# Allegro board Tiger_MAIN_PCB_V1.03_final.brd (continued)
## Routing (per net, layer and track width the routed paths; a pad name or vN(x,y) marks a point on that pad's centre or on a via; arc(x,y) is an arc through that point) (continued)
GND_EARTH: length 5.3
  TOP w0.406: v2(100.89,25.46) C401.1 102.17,28.36 C400.1 102.17,28.63 C402.2 102.18,29.41 C399.2
  vias: v1(81.7,22.25) v1(81.7,21.36) v1(81.7,20.47) v2(107.05,42.35) v2(107.05,40.53) v2(107.06,39.4) v2(107.06,37.58) v2(108.16,29.18) v2(108.2,42.12) v2(108.21,40.37) v2(108.27,38.2) v2(108.22,32.34) v2(108.29,35.24)
V1.05A_PWRGD: length 114.6
  TOP w0.254: v2(164.11,48.34) R767.1 164.89,47.9 165.68,47.11 165.68,46.63 165.43,46.38 U41.6
  LAY6 w0.102: v2(164.11,48.34) 163.26,49.2 156.67,49.2 155.35,47.87 146.17,47.87 142.89,51.15 118.33,51.15 113.42,56.07 98.24,56.07 97.35,56.96 92.7,56.96 91.94,57.72 73.65,57.72 72.97,57.03 66.45,57.03 66.02,56.6 v2(61.12,56.6)
  BOTTOM w0.102: v2(61.12,56.6) 61.12,56.97 60.71,57.37 60.08,57.37 59.92,57.22 U22.34
V1.5S_PWRGD: length 113.8
  TOP w0.102: v2(138.59,57.5) 138.6,57.5 139.04,57.95 144.57,57.95 144.78,57.74 R537.2 144.96,57.24 U35.7
  LAY3 w0.102: v2(50.23,67.89) 50.68,67.45 50.68,57.81 v2(50.93,57.55)
  LAY6 w0.102: v2(138.59,57.5) 138.26,57.83 135.39,57.83 135.09,57.53 133.5,57.53 132.73,58.3 119.21,58.3 116.64,60.87 115.58,60.87 114.67,61.79 114.67,62.55 114.28,62.94 82.47,62.94 79.88,65.53 66.43,65.53 64.39,67.56 50.56,67.56 v2(50.23,67.89)
  BOTTOM w0.102: v2(50.93,57.55) 50.72,57.34 U22.57
V1.8A_PWRGD: length 2.5
  BOTTOM w0.203: U70.4 155.05,51.04 155.35,51.34 156.62,51.34 R774.2
V1P0_DRVH: length 13.9
  TOP w0.254: U41.13 161.51,44.25 161.05,43.79
  TOP w0.635: v1(160.15,43.44) 160.7,43.44 161.05,43.79 ; R765.1 159.74,53.22 v1(159.89,53.07)
  LAY3 w0.635: v1(160.15,43.44) 159.63,43.44 158.64,44.43 158.64,48.52 159.89,49.77 v1(159.89,53.07)
V1P0_DRVL: length 2.2
  TOP w0.254: U41.9 161.51,46.66
  TOP w0.635: 161.51,46.66 161.51,48.61 R768.1
V1P0_LL: length 35.6
  TOP w0.254: U41.12 160.92,44.88 160.83,44.79 ; R392.2 165.58,40.83 165.08,40.33 163.82,40.33 163.07,41.09 163.07,41.8 C344.1 163.05,42.02 v2(162.73,42.34)
  TOP w0.635: 160.83,44.79 160.46,44.42 v1(159.97,44.42)
  LAY3 w0.635: v1(159.97,44.42) 161.61,46.06 v1(161.61,57.01)
  BOTTOM w0.254: v2(162.73,42.34) 161.51,43.56 161.51,47.82 161.96,48.27 161.96,56.32 v2(162.54,56.9)
VBAT: length 2.4
  BOTTOM w0.203: U22.3 62.8,69.46 R381.2 63.2,69.86 R390.2
VCC1_USB3.0: length 4
  TOP w0.635: CN36.1 v1(11.95,92.82)
  BOTTOM w0.305: R339.2 19.77,89.27 19.77,88.26 19.18,87.66
VCC2_USB3.0: length 3.5
  TOP w0.762: v1(38.86,92.15) 38.85,92.16 CN24.1
  BOTTOM w0.305: R559.2 46.17,88.93
VCC_8625: length 41
  TOP w0.305: R2999.2 134.55,76.1 134.05,75.6 ; 132.21,75.6 131.53,75.6 ; 132.21,75.6 131.88,75.93 131.88,75.95 ; 132.21,75.6 134.05,75.6 ; 131.53,75.6 130.32,75.6 130,75.92 U2527.8 130,78.71 R2988.2 ; 131.53,75.6 131.88,75.95 ; 131.88,75.95 131.88,78.67 R2998.2 ; 134.05,75.6 135.04,74.61 U2525.8 135.6,75.53 v2(136.33,76.26) 136.34,76.27 R2991.1 ; R2992.1 v2(140.45,76.27)
  LAY3 w0.305: v2(140.45,76.27) 142.1,76.27 143.02,77.19 146.15,77.19 v2(147.73,78.76)
  BOTTOM w0.203: U2526.13 144.14,82.01 144.58,81.58 144.58,81.34 144.25,81.34 143.98,81.61 U2526.14
  BOTTOM w0.305: v2(136.33,76.26) 140.44,76.26 v2(140.45,76.27)
  BOTTOM w0.508: v2(147.73,78.76) 147.6,78.89 146.55,78.89 145.7,79.75 C2766.1 145.53,79.75 144.58,80.7 144.58,81.34
  BOTTOM w0.762: FB45.1 147.87,77.71 FB39.1 147.87,78.62 v2(147.73,78.76)
VCC_USB2: length 6.6
  TOP w0.203: R569.2 44.11,24.26 44.11,19.64 F4.2
VCC_USB3: length 3.4
  TOP w0.203: R570.2 62.7,17.44 63.07,17.06
VCCCORE_SENSE: length 80.5
  TOP w0.076: U1.E32 v2(205.19,74.95)
  LAY3 w0.305: v2(205.19,74.95) 206.22,75.98 206.22,81.63 208.65,84.06 209.41,84.06 210.57,85.22 220.35,85.22 221.06,85.93 225.27,85.93 226.47,84.73 233.41,84.73 236.14,82 241.25,82 242.55,83.29 248.35,83.29 250,84.95 250,97.48 247.88,99.6 244.61,99.6 v2(241.74,102.47)
  BOTTOM w0.305: R683.2 241.27,102.94 v2(241.74,102.47)
VCCCORE_SENSE_IC: length 9.1
  BOTTOM w0.203: U103.17 238.57,92.14
  BOTTOM w0.305: 238.57,92.14 238.57,95.22 238.81,95.46 238.81,97.55 238.42,97.95 R222.2 239.26,98.38 R227.2 R226.2
VCCGT_SENSE: length 21.1
  TOP w0.076: 230.09,73.67 229.45,73.03 229.15,73.03 228.55,72.43 227.6,72.43 227.48,72.3 227.05,72.3 226.8,72.42 226.8,72.43 226.8,72.43 226.66,72.57 U1.J70
  TOP w0.102: 230.09,73.67 230.14,73.72 237.22,73.72 237.51,74.01
  TOP w0.203: R667.1 237.56,80.92 238.4,80.08 238.4,74.9 237.51,74.01
VCCRTCEXT: length 0.9
  TOP w0.203: U1.BB10 192.09,54.38 v2(192.15,54.32)
VCCSA_IMON: length 7.2
  BOTTOM w0.152: C319.1 R233.2
  BOTTOM w0.203: U103.23 241.6,89.92 242.66,90.97 242.66,92.88 242.93,93.15 R233.2
VCCSA_SENSE: length 79.9
  TOP w0.254: v2(197.81,72.65) 197.68,72.78 U1.H20
  LAY3 w0.254: v2(204.83,78.24) 204.82,78.25 204.82,82.32 209.02,86.52 219.72,86.52 220.59,87.38 230.57,87.38 231.16,87.97 231.98,87.97 235.45,84.5 236.67,84.5 237.42,83.75 238.55,83.75 239.3,84.5 247.25,84.5 248.76,86.01 248.76,95.73 248.41,96.08 248.41,96.86 247.93,97.34 246.97,97.34 v2(245.92,98.4)
  LAY6 w0.254: v2(197.81,72.65) 197.99,72.65 198.75,73.41 199.34,73.41 199.57,73.19 202.61,73.19 203.1,73.68 203.1,76.37 203.76,77.03 204.5,77.03 204.83,77.36 v2(204.83,78.24)
  BOTTOM w0.254: R674.1 245.39,98.4 v2(245.92,98.4)
VCCSA_SENSE_IC: length 12.5
  BOTTOM w0.203: R231.2 243.75,89.66 243.2,89.12 U103.25 ; R231.2 244.38,88.44 R185.2 ; R231.2 245.09,90.38 245.79,90.38 246.09,90.68 246.09,94.31 245.51,94.89 R230.2
VCCST_PWRGD: length 228.1
  TOP w0.076: R22.2 231.82,83.55 R20.2 232.15,83.96 v2(232.42,83.69)
  TOP w0.102: Q1.3 47.31,74.48 47.54,74.71 v2(47.54,76.49)
  LAY3 w0.102: v2(49.6,93.3) 47.54,91.25 v2(47.54,76.49)
  LAY6 w0.102: v2(232.42,83.69) 231.88,84.22 229.37,84.22 226.44,81.29 225.15,81.29 223.03,79.17 219.52,79.17 218.41,80.28 218.41,84.18 215.94,86.65 209.54,86.65 208.51,87.68 207.22,87.68 205.99,88.92 205.99,89.18 200.14,95.02 192.43,95.02 189.78,92.36 181.44,92.36 180.38,93.42 171.96,93.42 170.31,95.07 150.37,95.07 142.07,86.76 135.64,86.76 134.27,88.13 131.53,88.13 129.02,90.64 121.26,90.64 118.98,88.35 98.54,88.35 97.95,87.75 90.78,87.75 88.92,89.62 84.74,89.62 82.01,92.35 60.38,92.35 60.01,91.98 58.14,91.98 57.7,91.54 51.36,91.54 v2(49.6,93.3)
VCCST_PWRGD_MCP: length 12.8
  TOP w0.076: U1.B65 223.09,77.11 223.09,78.44 223.9,79.25 223.9,79.92 224.56,80.59 230.79,80.59 231.32,81.11 231.32,81.69 R22.1
VCCSTG_EN: length 10.7
  TOP w0.102: R660.2 166.28,56.31 v2(166.1,56.5) ; v2(168.12,62.47) 168.38,62.47 168.91,61.94 U67.3
  BOTTOM w0.102: v2(166.1,56.5) 165.32,57.27 165.32,61.53 166.1,62.3 167.95,62.3 v2(168.12,62.47)
VCCSTG_EN_R: length 1.6
  TOP w0.102: U6.4 167.05,55.6 R660.1
VDD12: length 13.6
  TOP w0.406: v2(143.23,76.05) 144.55,76.05 145.86,77.36 FB38.2
  BOTTOM w0.203: 141.35,80.37 U2526.19
  BOTTOM w0.305: C2767.1 141.96,75.83 141.24,76.54 141.24,77.44 141.85,78.05 C2771.2 C2768.2 141.85,79.87 141.35,80.37
VDD18: length 1.2
  BOTTOM w0.203: U95.18 71.14,98.41 C2785.2
VDDIO_8625: length 17.3
  TOP w0.203: C2764.2 140.55,88.8 v2(140.55,88.38)
  LAY3 w0.305: v2(139.22,77.69) 139.96,78.44 144.04,78.44 145.93,80.34 148.79,80.34 v2(149.06,80.07)
  BOTTOM w0.203: U2526.38 v2(136.11,85.21) C2765.2 ; R2989.2 R2990.2 149.26,80.26 v2(149.06,80.07) ; v2(140.55,88.38) U2526.50
  BOTTOM w0.305: R2993.2 v2(139.22,77.69) 139.49,77.42 R2996.2
VDDRX: length 4.6
  TOP w0.406: FB38.1 145.85,82.94 C2772.2 C2773.2 145.84,84.81 v2(145.2,84.81)
  BOTTOM w0.203: U2526.6 144.7,84.81
  BOTTOM w0.406: C2774.2 145.82,84.81 v2(145.2,84.81) 144.7,84.81
VIN_LCD: length 14.5
  TOP w0.305: U2529.13 127.62,86.7 v2(128.08,87.16)
  TOP w0.406: R3090.2 116.8,88.62 R3089.2 116.8,90.71 v2(117.19,91.09)
  LAY3 w0.203: v2(128.08,87.16) 124.19,91.05 v2(119.82,91.05)
VSSCORE_SENSE: length 80.1
  TOP w0.076: U1.E33 v2(205.19,74.32)
  LAY3 w0.305: v2(205.19,74.32) 205.08,74.32 204.64,74.76 204.64,75.19 205.81,76.36 205.81,81.97 209.45,85.61 220.18,85.61 220.89,86.33 225.78,86.33 226.92,85.19 233.55,85.19 235.03,83.7 236.33,83.7 237.57,82.46 241.06,82.46 242.31,83.7 247.96,83.7 249.6,85.34 249.6,97.16 247.68,99.08 244.2,99.08 242.16,97.04 v2(241.15,97.04)
  BOTTOM w0.203: R684.2 v2(241.15,97.04)
VSSCORE_SENSE_IC: length 5.8
  BOTTOM w0.203: U103.18 238.97,94.41 C317.2 239.5,94.94 R682.2 239.5,97.03 R684.1
VSSGT_SENSE: length 21.2
  TOP w0.076: U1.J69 226.06,72.57 226.33,72.3 226.61,72.3 227.02,72.14 227.55,72.14 227.67,72.27 228.62,72.27 229.22,72.86 230.24,72.86 230.89,73.52
  TOP w0.102: 237.72,73.77 237.47,73.52 230.89,73.52
  TOP w0.203: R668.1 239.43,80.9 238.7,80.17 238.7,74.75 237.72,73.77
VSSSA_SENSE: length 75.4
  TOP w0.254: U1.H21 198.34,72.79 198.77,72.79 v2(198.84,72.86)
  LAY3 w0.254: v2(249.01,96.45) 249.17,96.3 249.17,85.72 247.55,84.11 242.07,84.11 240.86,82.9 237.7,82.9 236.49,84.11 235.25,84.11 232.51,86.85 220.62,86.85 219.89,86.12 209.3,86.12 205.25,82.08 205.25,79.15 v2(205.3,79.1)
  LAY6 w0.254: v2(198.84,72.86) 198.91,72.78 202.84,72.78 203.51,73.45 203.51,76.25 203.85,76.59 204.63,76.59 205.3,77.26 v2(205.3,79.1)
  BOTTOM w0.254: R675.1 v2(249.01,96.45)
VSSSA_SENSE_IC: length 17
  BOTTOM w0.203: U103.26 242.33,88.72 243.48,87.56 R673.2 243.49,87.18 244.58,87.18 ; R675.2 248.43,87.72 247.55,86.85 244.91,86.85 244.58,87.18 ; 244.58,87.18 C320.2
8625_PD#: length 6.5
  BOTTOM w0.152: R2990.1 148.04,80.44 145.94,80.44 145.7,80.68 C2770.2 145.48,80.9 145.12,81.26 145.12,82.26 144.16,83.21 U2526.10
8625_PWMO: length 19.4
  TOP w0.203: R528.2 v2(129.89,88.79)
  LAY3 w0.102: v2(142.97,81.93) 142.59,82.3 142.59,85.57 141.29,86.86 131.82,86.86 v2(129.89,88.79)
  BOTTOM w0.152: U2526.12 143.37,82.41 142.97,82.01 v2(142.97,81.93)
8625_RST#: length 5.8
  BOTTOM w0.152: U2526.9 144.19,83.61 145.74,82.06 C2769.2 145.74,81.74 146.14,81.35 147.93,81.35 R2989.1
+V_ADP_IN: length 20.7
  BOTTOM w0.305: R791.2 144.21,13.28 R788.2 C784.2 141.02,13.28 140.29,14.02 140.29,18.37
  BOTTOM w1.016: 133.96,18.52 133.96,17 132.61,15.64 126.32,15.64 124.97,14.29 R303.2
+VSYS_DCIN: length 85.7
  TOP w0.305: v2(218.04,103.27) 218.51,103.74 246.56,103.74 249.74,100.57 249.74,93.26 249.13,92.65 249.13,87.21 245.93,84.01 v2(240.7,84.01)
  LAY3 w0.406: v1(206.65,99.22) 209.17,101.75 217.45,101.75 218.04,102.33 v2(218.04,103.27)
  BOTTOM w0.203: 15.44,73.57 15.56,73.44 U71.12 ; U103.33 238.97,85.73
  BOTTOM w0.305: C293.1 240.7,83.87 v2(240.7,84.01) 238.97,85.73
  BOTTOM w0.406: 15.44,73.57 15.18,73.82 C775.2 15.5,74.93 15.91,75.33 15.91,76.68 17.38,78.15 17.38,80.51 v2(15.56,82.34)
  vias: v1(118.2,80.5) v1(146.01,65.58) v1(146.01,64.56) v1(146.01,63.55) v1(147.02,65.58) v1(147.02,64.56) v1(147.02,63.55) v1(167.32,101.67) v1(168.08,101.67) v1(168.84,101.67) v1(169.6,101.67) v1(204.36,99.22) v1(205.12,99.22) v1(205.89,99.22) v2(118.99,80.46)
A_POWER_OK: length 191.9
  TOP w0.076: U1.BB20 197.49,54.28 196.74,53.53 196.74,52.66 196.25,52.17 196.25,51.68 194.05,49.49 v2(194.05,49.2)
  LAY3 w0.102: v2(42.94,53.49) 42.64,53.79 42.64,58.99 41.9,59.72 41.9,63 42.56,63.66 v2(42.56,68.23)
  LAY6 w0.102: v2(42.94,53.49) 43.67,52.76 54.32,52.76 55.39,53.83 75.13,53.83 76.87,52.09 89.21,52.09 89.49,52.37 92,52.37 94.02,50.35 108.76,50.35 109.71,51.3 113.21,51.3 117.07,47.44 123.13,47.44 125.04,45.54 129.89,45.54 130.96,46.6 133.84,46.6 133.99,46.76 139.27,46.76 146.07,39.96 165.71,39.96 166.67,40.92 172.84,40.92 173.35,40.41 175.89,40.41 176.23,40.75 179.72,40.75 v2(180.02,40.46)
  BOTTOM w0.076: R17.1 194.19,49.34 v2(194.05,49.2) 194.05,49.09 193.71,48.75 193.71,44.56
  BOTTOM w0.102: v2(42.56,68.23) 42.62,68.29 R409.2 ; v2(180.02,40.46) 180.47,40.92 191.47,40.92 193.71,43.15 193.71,44.56
AC_PRESENT: length 173
  TOP w0.076: v2(191.81,49.41) 191.89,49.49 191.89,50.3 195.51,53.92 195.51,55.28 195.4,55.39 195.4,55.67 U1.AY15
  LAY3 w0.076: v2(191.81,49.41) 191.06,48.66 191.06,46.43 187.67,43.04 182.3,43.04 180.87,44.47 176.75,44.47 v2(176.47,44.76)
  LAY3 w0.102: v2(56.86,70.53) 56.86,55.56 v2(57.03,55.39)
  LAY6 w0.076: v2(176.47,44.76) 176.13,44.76
  LAY6 w0.102: 176.13,44.76 171.78,44.76 171.16,44.14 165.99,44.14 163.14,41.28 146.27,41.28 139.88,47.67 130.87,47.67 130.13,46.93 125.91,46.93 124.59,48.26 117.84,48.26 113.85,52.24 97.5,52.24 96.22,53.53 92.41,53.53 91.7,54.24 85.07,54.24 84.4,54.91 57.51,54.91 v2(57.03,55.39)
  BOTTOM w0.102: R10.2 191.44,49.78 v2(191.81,49.41) ; v2(56.86,70.53) 56.86,70.76 57.12,71.02 U22.120
AC_VREF: length 3.8
  BOTTOM w0.203: C428.1 9.37,17.27 C432.2 9.5,17.86 9.89,17.48 10.51,17.48 10.99,17.96 U16.28
ADP_IN#: length 2.6
  BOTTOM w0.102: U22.71 45.85,60.26 45.45,59.85 45.45,59.49 R405.2
ALL_SYS_PWRGD_VRON: length 218.4
  LAY3 w0.087: v2(59.61,75.38) 60.62,76.4 60.62,86.34 59.42,87.55 v2(59.42,93.25)
  LAY6 w0.102: v2(235.78,86.37) 233.12,86.37 231.78,85.03 229.39,85.03 226.21,81.85 224.92,81.85 222.79,79.72 219.75,79.72 218.96,80.51 218.96,84.53 216.17,87.32 209.69,87.32 207.17,89.85 206.16,89.85 200.39,95.61 192.18,95.61 189.64,93.07 181.86,93.07 180.91,94.02 172.26,94.02 169.96,96.33 150.79,96.33 141.92,87.46 135.9,87.46 134.61,88.74 131.76,88.74 127.71,92.79 114.69,92.79 112.29,90.39 86.44,90.39 83.72,93.11 59.56,93.11 v2(59.42,93.25)
  BOTTOM w0.109: v2(235.78,86.37) U103.40 ; v2(59.61,75.38) 59.61,75.38 R402.1
AUD_MIC1_IN_L: length 24.5
  LAY6 w0.305: v2(13.87,10.21) 14.42,9.66 22,9.66 26.66,14.32 26.66,18.49 27.83,19.65 v2(27.83,20.87)
  BOTTOM w0.203: v2(13.87,10.21) 13.78,10.21 13.41,10.58 R355.1 13.41,10.81 R3121.2
  BOTTOM w0.305: R348.2 27.62,20.66 v2(27.83,20.87)
AUD_MIC1_IN_R: length 32.3
  LAY6 w0.305: v2(11.04,10.02) 12.98,10.02 13.85,9.15 22.15,9.15 27.16,14.16 27.16,17.92 29.19,19.95 32.82,19.95 v2(33.42,20.55)
  BOTTOM w0.203: R3120.2 10.99,10.8 R356.1 10.99,10.07 v2(11.04,10.02)
  BOTTOM w0.305: R347.2 33.87,20.09 v2(33.42,20.55)
AUD_MIC_IN_L: length 2
  BOTTOM w0.203: U16.17 15.13,14.78 C2845.2
AUD_MIC_IN_R: length 1.9
  BOTTOM w0.203: U16.18 14.73,14.53 C2844.2
AUDIO_DVDD_IO: length 5.6
  BOTTOM w0.203: 18.41,17.87 18.32,17.96 U16.9
  BOTTOM w0.406: 18.41,17.87 19,17.28 C454.2 19.98,17.28 R361.1 20.16,15.88 ; 20.16,15.88 20.16,14.64 R831.1 ; 20.16,15.88 R360.1
AUXN_LVDS: length 2.9
  BOTTOM w0.109: U2526.1 144.31,86.81 144.38,86.74 144.52,86.74 144.73,86.94 144.73,87.39 145.19,87.85 145.58,87.85 C2848.1
AUXP_LVDS: length 3
  BOTTOM w0.109: C2849.1 145.55,87.63 145.28,87.63 144.95,87.3 144.95,86.85 144.62,86.52 144.41,86.52 144.31,86.41 U2526.2
BAT-DEK#: length 0.9
  BOTTOM w0.102: R419.2 43.02,57.88 R406.1
BKUP_BAT: length 5.6
  BOTTOM w0.508: R182.2 86.5,85.12 CN7.1
BL_ADJ: length 124.4
  TOP w0.203: R2985.1 137.85,90.47 137.43,90.05 132.61,90.05 132.02,90.64 130.33,90.64 130.06,90.36 R3109.1 129.34,93.88 v2(128.19,95.03)
  LAY3 w0.102: v2(60.17,95.4) 60.17,92.78 59.78,92.4 59.78,87.84 60.94,86.69 60.94,76.07 60.36,75.48 60.36,70.24 60.99,69.6 60.99,66.42 59.9,65.32 v2(59.9,59.3)
  LAY6 w0.102: v2(128.19,95.03) 103.31,95.03 102.08,93.8 98.65,93.8 96.55,95.89 81.06,95.89 80.56,95.4 v2(60.17,95.4)
  BOTTOM w0.102: U22.30 60.16,58.66 59.9,58.92 v2(59.9,59.3)
BLCTL: length 114.5
  TOP w0.102: v2(135.1,77.45) 135.1,78.39 135.55,78.85 135.55,80.98 R454.2 134.81,81.02 134.24,81.59 U27.1
  LAY3 w0.102: v2(64.6,86.32) 64.28,86 64.28,69.68 64.45,69.52 64.45,63.78 64.88,63.34 64.88,58.03 v2(64.37,57.53)
  LAY6 w0.102: v2(64.6,86.32) 64.79,86.13 84.64,86.13 94.26,76.5 102.86,76.5 105.33,78.96 113.94,78.96 116.96,75.94 124.76,75.94 126.61,77.8 129.77,77.8 130.12,77.45 v2(135.1,77.45)
  BOTTOM w0.102: v2(64.37,57.53) R466.2 R415.1
BT_ON: length 104.1
  LAY3 w0.102: v2(70.81,35.15) 70.76,35.2 v2(70.76,59.71)
  LAY6 w0.102: v2(70.81,35.15) 71.3,34.65 80.1,34.65 81.63,36.18 84.32,36.18 90.99,42.85 93.8,42.85 98.11,47.16 106.62,47.16 108.91,44.88 112.35,44.88 114.66,42.57 117.58,42.57 118.94,41.21 118.94,30.48 122.59,26.83 v2(127.97,26.83)
  BOTTOM w0.102: R457.2 v2(70.76,59.71) ; R3007.2 127.97,27.61 R196.1 v2(127.97,26.83)
BT_RF_KILL_R*: length 2.8
  TOP w0.102: CN26.54 v2(130.49,26.61)
  BOTTOM w0.102: v2(130.49,26.61) 130.49,27.28 130.17,27.61 R3007.1
CA_VREF_CHB: length 12.8
  TOP w0.102: CN1.164 196.62,15.84 v2(196.12,16.34)
  BOTTOM w0.305: R476.2 194.25,12.77 R368.2 193.39,12.8 R45.1 193.38,14.03 193.38,17.11 192.96,17.52 C416.2 193.84,17.8 C250.2 194.6,17.63 195.89,16.34 v2(196.12,16.34)
CFG<0>: length 8.7
  TOP w0.076: U1.E68 224.52,75.83 224.45,76.09 224.41,76.35 224.36,76.54 224.31,76.69 224.31,76.73 224.31,76.74 224.31,76.85 224.31,76.91 224.33,76.99 224.34,77.08 224.34,77.22 224.31,77.32 224.31,77.67 224.31,77.68 224.31,77.83 224.46,77.98 224.46,78.33 225.12,79 R717.2
CFG<1>: length 6.1
  TOP w0.076: U1.B67 224.74,76.95 225.07,77.28 225.07,77.55 225.27,77.74 225.91,78.39 229.85,78.39 R722.2
CFG<2>: length 11.4
  TOP w0.076: U1.D65 223.39,75.7 223.07,76.03 223.07,76.28 223.24,76.46 223.46,76.46 223.63,76.63 arc(223.65,76.65) 223.65,76.68 223.65,76.86 223.63,76.92 223.61,76.99 223.61,76.99 arc(223.59,77.02) 223.59,77.05 223.59,77.2 arc(223.59,77.23) 223.61,77.25 223.65,77.3 223.65,77.6 223.5,77.75 223.5,78.36 224.68,79.54 230.44,79.54 R723.2
CFG<3>: length 9.7
  TOP w0.076: R724.2 231.55,78.63 224.99,78.63 224.63,78.26 224.63,77.91 224.48,77.76 224.48,77.34 224.53,77.23 224.53,77.08 224.48,76.89 224.48,76.71 224.56,76.46 U1.D67
CFG<4>: length 3.3
  TOP w0.102: R721.1 228.4,75.98 228.17,75.74 227.72,75.74 227.31,75.34 226.96,75.34 226.77,75.15 U1.E70
CFG<5>: length 7.3
  TOP w0.076: U1.C68 226.17,76.47 226.66,76.47 226.84,76.65 227.46,76.65 227.64,76.47 228.12,76.47 228.71,77.05 230.33,77.05 230.7,77.42 231.53,77.42 R727.2
CFG<6>: length 5.8
  TOP w0.076: U1.D68 226.6,75.67 226.93,76 228.07,76 228.96,76.89 230.51,76.89 230.68,77.06 R726.2
CFG<8>: length 3.4
  TOP w0.076: R725.2 228.72,75.08 228.22,74.59 226.77,74.59 U1.F71
CFG<9>: length 4.4
  TOP w0.076: U1.G69 226.09,73.56 227.41,73.56 227.75,73.91 228.75,73.91 229.08,74.25 R728.2
CFG<10>: length 6.8
  TOP w0.076: R729.2 231.57,76.18 231.1,76.18 230.94,76.01 230.94,75.66 230.76,75.48 228.8,75.48 228.09,74.77 227,74.77 226.99,74.79 226.38,74.79 U1.F70
CFG<12>: length 6.3
  TOP w0.076: R730.2 231.52,73.93 229.63,73.93 228.63,72.93 226.49,72.93 U1.H70
CFG<13>: length 5.8
  TOP w0.076: 231.04,74.59 229.11,74.59 228.6,74.08 227.33,74.08 U1.G71
  TOP w0.102: R731.2 231.85,75.4 231.04,74.59
CHAGER_IOUT: length 251.7
  LAY3 w0.102: v2(43.74,92.88) 40.66,89.8 40.66,58.67 41.46,57.87 v2(41.46,57.06)
  LAY6 w0.102: v2(43.74,92.88) 45.62,92.88 47.25,91.26 57.97,91.26 58.45,91.74 60.1,91.74 60.5,92.13 81.94,92.13 84.73,89.34 88.73,89.34 91.09,86.98 104.01,86.98 105.17,88.15 119.06,88.15 121.35,90.43 128.94,90.43 131.44,87.93 134.07,87.93 135.48,86.52 142.11,86.52 150.42,94.83 170.19,94.83 171.79,93.22 180.2,93.22 181.29,92.13 189.84,92.13 192.52,94.81 200.06,94.81 205.57,89.31 205.57,89.01 208.11,86.46 215.86,86.46 218.22,84.1 218.22,80.2 219.44,78.98 223.1,78.98 225.23,81.1 226.52,81.1 228.48,83.05 231.81,83.05 231.86,83.1 v2(232.4,83.1)
  BOTTOM w0.102: v2(232.4,83.1) 231.92,83.1 R218.1
  BOTTOM w0.203: R236.2 41.49,57.03 v2(41.46,57.06)
CORE_BOO: length 1.2
  BOTTOM w0.254: U45.2 180.14,95.97 180.15,95.96
  BOTTOM w0.635: 180.15,95.96 R239.2
CORE_CSP: length 13
  BOTTOM w0.203: R242.1 R213.2 R214.1 241.78,99.69 C299.1 241.78,98.75 C307.2 242.39,97.84 241.64,97.09 241.64,94.05 241.34,93.75 240.59,93.75 239.37,92.53 U103.19
CORE_FCCM: length 73.9
  LAY6 w0.635: v1(240.98,92.02) 239.01,93.99 234.37,93.99 233.58,94.78 215.98,94.78 215.73,94.53 208.4,94.53 206.64,96.28 204.92,96.28 202.09,99.11 187.12,99.11 186.52,99.7 177.59,99.7 176,98.11 176,96.63 v1(175.98,96.6)
  BOTTOM w0.203: U103.21 240.52,91.25
  BOTTOM w0.254: v1(175.98,96.6) 175.98,96.55 176.56,95.97 U45.7
  BOTTOM w0.635: 240.52,91.25 240.52,91.56 v1(240.98,92.02)
CORE_HG_DRV: length 4.9
  BOTTOM w0.254: 179.45,97.08 179.45,97.08 U45.1
  BOTTOM w0.635: 179.45,97.08 179.45,97.21 182.27,100.02 R689.1
CORE_LG_DRV: length 10
  BOTTOM w0.254: 177.83,94.41 177.55,94.69 U45.5
  BOTTOM w0.635: R690.1 186.4,93.8 178.44,93.8 177.83,94.41
CORE_PHASE: length 61.8
  TOP w0.635: v1(176.9,96.7) 182.52,96.7 183.35,97.53
  LAY6 w0.254: v2(194.69,100.27) 195.33,100.91 209.7,100.91 210.8,102.01 232.25,102.01 234.09,103.86 242.77,103.86 v2(244.42,102.2)
  BOTTOM w0.203: R242.2 v2(244.42,102.2)
  BOTTOM w0.254: v1(176.9,96.7) 177.12,96.47 U45.8
  BOTTOM w0.635: C721.2 183.16,97.57 v1(183.88,98.29)
CORE_PWM1: length 68.4
  LAY6 w0.635: v1(182.7,95.74) 182.87,95.74 184.96,97.82 201.43,97.82 204.33,94.92 206.15,94.92 208.67,92.4 235.15,92.4 236.46,91.09 241.53,91.09 v1(241.67,91.23)
  BOTTOM w0.203: U103.22 241.11,90.32 241.4,90.61
  BOTTOM w0.254: U45.3 179.84,95.47 180.17,95.14
  BOTTOM w0.635: v1(182.7,95.74) 182.7,95.46 182.2,94.96 180.35,94.96 180.17,95.14 ; 241.4,90.61 241.67,90.87 v1(241.67,91.23)
CPU_POPIRCOMP: length 20.7
  TOP w0.254: U1.AT16 v2(196.05,58.24)
  TOP w0.305: R41.1 v2(181.2,49.09)
  LAY6 w0.203: 195.2,57.07 195.57,57.44 195.57,57.77 v2(196.05,58.24)
  LAY6 w0.254: 195.2,57.07 193.97,57.07 190.5,53.6 188.76,53.6
  LAY6 w0.305: v2(181.2,49.09) 181.2,50.35 184.45,53.6 188.76,53.6
CPU_SVIDALRT*: length 14
  TOP w0.076: v2(229.24,81.54) 228.92,81.54 228.81,81.65 228.81,83.11 ; 228.81,83.11 R125.2 ; 228.81,83.11 R122.1
  LAY6 w0.087: v2(229.24,81.54) 229.78,82.08 233.52,82.08 v2(234.17,82.72)
  BOTTOM w0.109: v2(234.17,82.72) 235.35,82.72 236.66,84.03 236.66,84.63 237.77,85.75 U103.36
CPU_SVIDCLK: length 16.8
  TOP w0.076: v2(227.97,81.55) 227.97,81.86 227.81,82.02 227.36,82.02 227.2,81.87 227.2,81.63 227.05,81.47 226.78,81.47 226.36,81.9 224.46,81.9 223.18,80.62 223.18,79.55 222.42,78.79 222.42,77.59 U1.A63
  LAY6 w0.087: v2(227.97,81.55) 228.71,80.82 231.65,80.82 v2(231.98,81.15)
  BOTTOM w0.109: v2(231.98,81.15) 232.5,81.15 R714.2 233.32,81.97 R715.2
CPU_SVIDDAT: length 21.5
  TOP w0.076: U1.D64 222.83,76.06 222.54,76.36 222.54,76.68 222.75,76.89 222.75,78.6 223.54,79.38 223.54,80.49 224.6,81.54 226.2,81.54 226.78,80.97 229.97,80.97 v2(230.54,81.54) 230.54,81.87 R124.2
  LAY6 w0.087: v2(230.54,81.54) 233.62,81.54 v2(234.16,81.01)
  BOTTOM w0.109: v2(234.16,81.01) 235.18,81.01 R713.1 236.47,81.62 R686.1
CSI2_COMP: length 3.7
  TOP w0.254: U1.E13 v2(194.22,74.95)
  BOTTOM w0.254: v2(194.22,74.95) 194.39,74.95 194.68,74.66 194.68,72.84 195.08,72.45 R80.1
DDR1_B_ALERT_N: length 61.2
  TOP w0.076: U1.AN43 v2(211.59,60.15)
  TOP w0.153: v2(203.81,17.39) 204.23,17.39 205.1,18.26 207.41,18.26 208.3,17.37 210.22,17.37 210.62,16.97 CN1.116
  LAY6 w0.076: v2(211.59,60.15) 211.58,60.15 211.04,59.61 211.04,57.98 210.77,57.72 210.77,54.76 211.13,54.4 211.13,51.55 212.5,50.18 212.5,44.98 212.87,44.61
  LAY6 w0.137: 212.87,44.61 212.87,40.3 207.4,34.84 207.4,30.53 202.7,25.83 202.7,18.28 203.59,17.39 v2(203.81,17.39)
  BOTTOM w0.076: R50.1 211.57,60.17 v2(211.59,60.15)
DDR1_B_PARITY: length 50.7
  TOP w0.076: U1.AP43 v2(211.59,59.51)
  TOP w0.102: v2(203.75,18.58) 203.86,18.69 CN1.143
  LAY6 w0.076: 213.14,44.62 212.73,45.03 212.73,50.28 211.36,51.65 211.36,54.42 210.99,54.78 210.99,57.46 211.22,57.69 211.22,59.14 v2(211.59,59.51)
  LAY6 w0.137: 213.14,44.62 213.14,40.19 207.67,34.73 207.67,30.23 202.98,25.54 202.98,19.35 v2(203.75,18.58)
DDR3VR_PWRGD: length 252.6
  LAY3 w0.102: v2(62.87,59.38) 62.54,59.05 62.54,51.71 v2(62.82,51.43) ; v2(242.75,42.59) 245.61,39.73 245.61,27.55 249.05,24.11 249.05,15.97 241.34,8.26 168.61,8.26 159.4,17.47 158.44,17.47 v2(156.89,19.02)
  LAY6 w0.102: v2(62.82,51.43) 73.54,51.43 74.73,50.24 87.72,50.24 89.25,48.71 92,48.71 92.46,48.26 92.46,47.82 92.98,47.3 94.37,47.3 96.5,49.44 110.04,49.44 110.76,50.16 111.46,50.16 116.1,45.53 121.21,45.53 122.43,44.31 130.69,44.31 131.26,43.73 132.94,43.73 133.32,44.12 135.73,44.12 151.66,28.19 151.66,24.25 v2(156.89,19.02)
  BOTTOM w0.102: U22.25 62.37,60.66 62.61,60.42 62.61,59.64 v2(62.87,59.38) ; R545.2 v2(242.75,42.59)
DDR4_DRAMRST#: length 107.1
  TOP w0.076: U1.AT13 193.46,58.89 v2(193.3,58.89)
  LAY3 w0.076: v2(193.3,58.89) 193.1,58.89 192.85,58.64 192.85,57.5 192.02,56.66 190.98,56.66 190.39,57.25 188.08,57.25 187.24,56.41 182.61,56.41 179.54,53.34 176.38,53.34
  LAY3 w0.102: 176.38,53.34 175.49,53.34 172.9,50.76 172.9,48.75 172.75,48.6 172.75,41.82 172.34,41.41 172.34,30.53 173.07,29.8 173.07,19.87 175.1,17.84 178.8,17.84 179.49,17.14 179.49,14.89 180.1,14.28 180.71,14.28 183.23,11.77 185.43,11.77 187.85,14.19 213.44,14.19 214.19,14.94 214.19,16.49 v2(214.62,16.92)
  BOTTOM w0.076: R502.1 214.2,16.92 v2(214.62,16.92)
DDR4_DRAMRST_R#: length 4.8
  TOP w0.076: v2(213.11,15.75) 212.62,15.25 CN1.108
  BOTTOM w0.076: v2(213.11,15.75) 213.7,15.75 R502.2 213.84,14.76 R498.1 214.37,14.76 C417.2
DDR_CA_VREF: length 12.6
  TOP w0.203: U1.AY67 224.74,56.02 225.35,55.42 v2(225.35,55.35)
  BOTTOM w0.203: v2(225.35,55.35) 225.91,54.79 225.91,45.64 226.21,45.34 R46.1 C7.2
DDR_PG_CTRL: length 32
  TOP w0.076: U1.AW67 225.23,56.77 225.29,56.83 225.84,56.83 225.91,56.9 226.38,56.9 v2(226.65,56.63)
  BOTTOM w0.203: v2(226.65,56.63) 226.65,52.79 227.65,51.79 230.6,51.79 232.2,53.39 238.41,53.39 238.99,53.97 240.91,53.97 242.4,52.48 242.4,44.95 242.15,44.7 U4.2
DDR_STBY: length 148
  LAY3 w0.102: v2(238.05,39.78) 238.05,41.33 236.89,42.5 233.64,42.5 230.73,39.59 230.73,37.6 244.32,24.01 244.32,19.72 243.81,19.21 243.81,14.32 239.91,10.42 192.83,10.42 192.64,10.61 182.57,10.61 180.24,12.94 173,12.94 166.22,19.72 166.22,28.96 v2(165.94,29.24)
  BOTTOM w0.102: R550.1 236.77,41.06 R551.1 237.54,41.07 R549.1 238.33,40.58 238.05,40.31 v2(238.05,39.78) 238.15,39.69 U29.5 ; R470.2 167.06,30.36 v2(165.94,29.24)
DDR_VREFDQ_CHA: length 11
  TOP w0.203: U1.AY68 225.88,55.87 v2(226.01,56.01)
  BOTTOM w0.203: v2(226.01,56.01) 226.2,55.82 226.2,47.15 226.45,46.9 C8.2 R47.1
DDR_VTT_PG_CTRL: length 3.7
  BOTTOM w0.102: R548.2 239.11,42.02 R549.2 238.33,42.87 R152.2 238.99,42.88 239.58,43.47 U4.4
DEVICE_PROCHOT*: length 260.4
  TOP w0.076: R36.1 231.82,80.5 R27.2 231.15,80.5 231.02,80.37 228.39,80.37 v2(227.94,79.92)
  TOP w0.109: R27.2 231.59,80.64 231.59,81.34 231.87,81.63 232.09,81.63 232.82,82.36 232.82,84.02 v2(232.59,84.25)
  LAY3 w0.087: v2(45.15,93.68) 44.76,93.29 43.41,93.29 40.04,89.91 40.04,88.65 37.84,86.46 37.84,61.48 37.44,61.08 v2(37.33,61.08)
  LAY6 w0.087: v2(45.15,93.68) 49.89,93.68 51.07,92.5 60.05,92.5 60.18,92.63 83.56,92.63 86.26,89.92 90.06,89.92 91.95,88.03 97.76,88.03 98.27,88.55 118.9,88.55 121.27,90.92 129.02,90.92 131.61,88.33 134.37,88.33 135.69,87 142.03,87 150.34,95.31 170.35,95.31 172.04,93.62 180.61,93.62 181.64,92.59 189.73,92.59 192.35,95.21 200.23,95.21 205.99,89.45 207.01,89.45 209.62,86.84 216.11,86.84 218.59,84.36 218.59,80.35 219.59,79.35 222.95,79.35 225.07,81.47 226.36,81.47 229.55,84.65 232.19,84.65 v2(232.59,84.25)
  BOTTOM w0.076: R685.2 232.89,84.55 v2(232.59,84.25)
  BOTTOM w0.102: v2(227.94,79.92) 227.94,80.47 TP17.1
  BOTTOM w0.109: v2(37.33,61.08) 37.34,61.09 C487.1 39.18,61.09 U23.4
DRVH1: length 1.5
  TOP w0.635: Q30.8 26,77.78 R787.1
DRVH2: length 1.4
  TOP w0.635: Q31.8 15.31,76.87 R783.2
DRVL1: length 2.1
  TOP w0.635: Q30.3 21.99,84.31 R786.1
DRVL2: length 2.4
  TOP w0.635: Q31.3 v1(11.34,80.59)
  BOTTOM w0.635: R781.2 11.46,80.71 v1(11.34,80.59)
EARPHONE_CTRL: length 93.9
  TOP w0.305: J3.6 35.04,23.74 32.89,21.6 27.45,21.6 26.23,20.38 26.23,13.33 25.11,12.21 18.78,12.21 v2(18.29,12.71)
  LAY3 w0.102: v2(43,63.52) 42.82,63.52 42.23,62.94 42.23,59.86 43.43,58.67 43.43,48.48 25.31,30.37 19.91,30.37 18.78,29.23 18.78,23 18.29,22.51 v2(18.29,12.71)
  BOTTOM w0.102: v2(43,63.52) R102.2 ; R358.1 v2(18.29,12.71)
EC_HID_INT*: length 4.1
  TOP w0.076: v2(192.39,58.24) 192.54,58.24 U1.AU11
  BOTTOM w0.102: TP13.1 192.86,61.3 192.86,58.72 v2(192.39,58.24)
EC_LPC_CLK: length 167.3
  TOP w0.076: 183.88,46.12 184.17,46.12 186.85,48.8 186.85,51.88 187.24,52.27 187.72,52.27 189,53.54 191.01,53.54 191.65,54.19 191.65,54.38 191.86,54.59 191.86,54.97 191.84,55 191.81,55.08 191.81,55.2 191.88,55.41 191.88,55.56 191.82,55.72 191.82,55.8 191.6,56.5 191.6,56.5 191.43,56.68 U1.AW9
  TOP w0.102: 183.88,46.12 181.88,44.13 181.88,37.66 180.4,36.18
  TOP w0.109: v2(79.74,64.55) 82.21,64.55 87.58,69.91 110.26,69.91 117.95,62.23 127.73,62.23 145.82,44.13 145.82,41.08 153.6,33.3 167.34,33.3 169.01,34.97 179.19,34.97 180.4,36.18
  BOTTOM w0.109: U22.13 62.46,65.46 62.72,65.2 67.58,65.2 69.17,63.61 78.8,63.61 v2(79.74,64.55)
EC_MUTE#: length 59.3
  TOP w0.102: v2(60.69,59.25) 60.69,58.1 59.29,56.7 48.37,56.7 30.99,39.33 28.64,39.33 25.93,36.61 25.93,31.99 23.88,29.94 20.58,29.94 v2(20.27,29.64)
  BOTTOM w0.102: v2(20.27,29.64) 19.89,29.26 19.89,29.25 R369.2 19.31,28.66 U17.1 ; U22.28 60.89,59.46 v2(60.69,59.25)
EC_PCH_RCIN*: length 158.1
  TOP w0.076: U1.AW13 193.85,56.68 194.02,56.5 194.02,56.5 194.06,56.37 194.24,55.8 194.24,55.72 194.3,55.56 194.3,55.41 194.23,55.2 194.23,55.08 194.28,54.96 194.28,54.59 194.14,54.44 194.14,53.69 192.11,51.67 191.05,51.67 190.11,50.73 v2(190.11,50.55) R92.2
  LAY3 w0.087: v2(67.89,70.29) 68.08,70.1 68.08,67.75 68.65,67.18 68.65,63.09 68.08,62.52 68.08,56.64 v2(68.05,56.61)
  LAY6 w0.076: 176.13,48.13 184.94,48.13 185.9,49.08 188.11,49.08 189.58,50.55 v2(190.11,50.55)
  LAY6 w0.087: v2(68.05,56.61) 68.5,56.61 68.65,56.46 75.09,56.46 75.34,56.71 77.4,56.71 78.17,55.94 84.94,55.94 85.34,55.54 92.4,55.54 93.36,54.58 96.84,54.58 97.62,53.81 114.06,53.81 118.43,49.44 119.51,49.44 120.12,50.05 125.29,50.05 126.73,48.61 131.86,48.61 133.05,49.81 139.65,49.81 147.02,42.44 156.61,42.44 157.84,43.67 157.84,44.38 159.96,46.5 163.75,46.5 164.03,46.22 174,46.22 175.9,48.13 176.13,48.13
  BOTTOM w0.109: v2(67.89,70.29) 67.87,70.28 R487.2
EDID_SCL: length 8
  TOP w0.102: v2(135.13,80.13) 134.68,80.59 133.71,80.59 133.13,80.01 133.13,79.06 R2998.1 132.54,78.47 U2527.6
  BOTTOM w0.102: U2526.29 136.76,81.61 136.18,81.03 136.04,81.03 v2(135.13,80.13)
EDID_SDA: length 6.7
  TOP w0.102: v2(134.46,80.16) 134.46,79.58 R2999.1 133.81,78.52 U2527.5
  BOTTOM w0.102: U2526.30 136.6,82.01 136.12,81.54 135.84,81.54 v2(134.46,80.16)
EDP_AUX_DN*: length 86.5
  TOP w0.076: v2(212.51,74.95) 212.28,74.73 U1.E45
  LAY6 w0.076: 212.63,76.73 212.62,76.72 212.62,75.88 212.11,75.37 212.11,74.8 212.19,74.72 212.27,74.72 v2(212.51,74.95)
  LAY6 w0.087: 212.63,76.73 212.63,77.28 214.68,79.34 214.68,83.82 213.07,85.44 206.35,85.44 200.09,91.7 192.58,91.7 191.84,90.96 180.83,90.96 179.49,92.29 171.37,92.29 169.91,93.76 155.13,93.76 149.2,87.83 148.14,87.83 v2(147.95,88.02)
  BOTTOM w0.109: v2(147.95,88.02) 147.76,87.83 147.06,87.83 C2848.2
EDP_AUX_DP: length 86.5
  TOP w0.076: v2(212.51,74.32) 212.27,74.08 U1.F45
  LAY6 w0.076: 212.45,76.79 212.45,75.95 211.94,75.44 211.94,74.73 212.12,74.55 212.27,74.55 v2(212.51,74.32)
  LAY6 w0.087: 212.45,76.79 212.45,77.35 214.51,79.41 214.51,83.75 213,85.26 206.28,85.26 202.78,88.76 202.77,88.76 200.01,91.52 192.66,91.52 191.92,90.78 180.75,90.78 179.42,92.11 171.3,92.11 169.83,93.58 155.21,93.58 149.28,87.65 148.17,87.65 v2(147.95,87.42)
  BOTTOM w0.109: C2849.2 147.06,87.61 147.76,87.61 v2(147.95,87.42)
EDP_BKLCTL_3P3: length 11.9
  TOP w0.203: R2997.1 135.2,89.67 R3123.1 132.37,89.07 131.96,88.65 131.96,88.37 Q48.3 130.55,88 R3107.2 130.53,89.57 R3110.2
EDP_BKLEN_OUT: length 5.1
  TOP w0.305: R3094.1 127.68,82.69 128.97,82.69 129.17,82.88 R541.2 130.09,82.88 R456.1 R453.1 130.96,82.21 R452.1
EDP_COMP: length 15.6
  TOP w0.254: U1.E52 v2(216.16,74.95) ; R59.1 225.9,83.28 v2(225.94,83.28)
  LAY3 w0.254: v2(216.16,74.95) 216.65,75.44 217.62,75.44 220.85,78.66 222.72,78.66 224.95,80.89 224.95,82.56 225.67,83.28 v2(225.94,83.28)
EDP_DISP_UTIL: length 6.3
  TOP w0.102: TP25.1 216.6,81.23 216.6,79.49 215.69,78.58 215.69,77.07 U1.B52
EDP_HPD: length 69.7
  TOP w0.076: U1.L10 v2(191.54,71.02)
  TOP w0.109: v2(143.12,82.81) 143.43,82.5 143.43,79.64 141.17,77.38 v2(141.17,68.87)
  LAY6 w0.076: v2(191.54,71.02) 191.17,71.39 183.14,71.39 182.34,72.2 179.28,72.2 178.96,71.88 177.6,71.88 177.28,71.56 176.81,71.56
  LAY6 w0.087: 176.81,71.56 172.7,71.56 172.04,72.22 153.45,72.22 151.06,69.83 142.13,69.83 v2(141.17,68.87)
  BOTTOM w0.076: v2(191.54,71.02) 191.83,71.31 R60.1
  BOTTOM w0.109: U2526.11 v2(143.12,82.81)
EDP_TX_DN*<0>: length 83
  TOP w0.076: U1.C47 213.22,76.41 213.22,78.02 213.45,78.25 213.45,79.6 213.09,79.97 212.78,79.97 v2(212.62,80.13)
  LAY6 w0.076: v2(212.62,80.13) 212.86,79.88 213.17,79.88 213.91,80.63 213.91,83.29 213.17,84.03 210.83,84.03 210.82,84.03 210.77,84.03 210.76,84.02 210.75,84.02
  LAY6 w0.087: 210.75,84.02 206.51,84.02 202.62,87.91 198.61,87.91 197.56,86.86 192.51,86.86 192.4,86.97 192.39,86.97 191.45,87.91 187.89,87.91 187.08,88.72 181.62,88.72 178.9,91.43 155.35,91.43 149.84,85.92 148.89,85.92 v2(148.65,85.68)
  BOTTOM w0.109: C281.1 147.06,85.87 148.45,85.87 v2(148.65,85.68)
EDP_TX_DN*<1>: length 84
  TOP w0.076: U1.D46 212.26,75.83 212.09,76 212.06,76.08 212.06,76.21 211.92,76.69 211.92,76.94 211.96,77.03 211.96,77.22 211.92,77.32 211.92,77.68 212.1,77.86 212.1,78.5 211.82,78.79 211.82,81.85 212.07,82.1 v2(212.62,82.1)
  LAY6 w0.076: 209.82,83.09 209.84,83.09 209.84,83.09 209.89,83.09 209.91,83.1 212.99,83.1 213.31,82.78 213.31,81.99 213.09,81.76 212.78,81.76 212.62,81.92 v2(212.62,82.1)
  LAY6 w0.087: v2(149.05,84.31) 149.25,84.51 150.72,84.51 156.27,90.06 171.1,90.06 171.71,90.67 178.28,90.67 181.02,87.93 186.8,87.93 187.58,87.14 190.98,87.14 191.92,86.2 191.93,86.2 192.04,86.08 198.16,86.08 199.22,87.14 201.85,87.14 205.91,83.09 209.82,83.09
  BOTTOM w0.109: v2(149.05,84.31) 148.85,84.5 148.52,84.5 148.28,84.26 148.28,83.78 147.85,83.34 147.07,83.34 C2846.1
EDP_TX_DP<0>: length 83
  TOP w0.076: v2(212.62,79.48) 212.62,79.59 212.83,79.8 213.02,79.8 213.29,79.53 213.29,78.32 213.05,78.09 213.05,76.61 U1.C46
  LAY6 w0.076: v2(212.62,79.48) 212.86,79.72 213.24,79.72 214.08,80.56 214.08,83.36 213.24,84.2 210.75,84.2
  LAY6 w0.087: v2(148.65,86.28) 148.82,86.11 149.76,86.11 155.27,91.61 178.98,91.61 181.69,88.9 187.15,88.9 187.96,88.09 191.53,88.09 192.52,87.1 192.52,87.09 192.58,87.03 197.49,87.03 198.54,88.08 202.7,88.08 206.58,84.2 210.75,84.2
  BOTTOM w0.109: C2850.1 147.06,86.09 148.45,86.09 v2(148.65,86.28)
EDP_TX_DP<1>: length 84
  TOP w0.076: U1.C45 212.4,76.11 212.57,76.11 212.64,76.18 212.64,76.32 212.5,76.46 212.22,76.46 212.14,76.54 212.09,76.71 212.09,76.9 212.12,77 212.12,77.25 212.09,77.34 212.09,77.61 212.26,77.79 212.26,78.57 211.98,78.86 211.98,81.78 212.14,81.94 212.27,81.94 212.62,81.59 v2(212.62,81.43)
  LAY6 w0.076: 209.82,83.26 209.83,83.27 213.06,83.27 213.48,82.85 213.48,81.92 213.15,81.59 212.78,81.59 v2(212.62,81.43)
  LAY6 w0.087: v2(149.05,84.91) 149.26,84.69 150.64,84.69 156.19,90.24 171.02,90.24 171.64,90.86 178.35,90.86 181.1,88.11 186.87,88.11 187.66,87.33 191.05,87.33 192.05,86.32 192.05,86.32 192.11,86.26 198.08,86.26 199.14,87.32 199.57,87.32 199.57,87.33 201.92,87.33 205.98,83.26 209.82,83.26
  BOTTOM w0.109: C2847.2 147.06,83.56 147.76,83.56 148.06,83.87 148.06,84.35 148.43,84.72 148.85,84.72 v2(149.05,84.91)
EDRAM_EDM: length 4.3
  TOP w0.076: U1.AY71 227.63,55.94
  TOP w0.102: 227.63,55.94 v2(227.81,55.76)
  BOTTOM w0.203: v2(227.81,55.76) 227.4,55.35 227.4,54.48 228.1,53.78 R720.2
EDRAM_OPIO_RCOMP: length 4.1
  TOP w0.203: U1.H66 v2(224.7,73.03)
  BOTTOM w0.254: v2(224.7,73.03) 223.96,72.3 223.47,72.3 223.15,71.98 223.15,71.47 R43.1
EECS: length 4.6
  BOTTOM w0.102: R310.2 130.44,40.7 U9.30
EEDI: length 4.4
  BOTTOM w0.102: U9.32 130.41,39.9 132.07,41.55 R308.2
EMC_THERM#: length 1.1
  TOP w0.254: R524.1 U5.4
EMMC_RCOMP: length 2.8
  TOP w0.203: R81.2 184.75,57.8 185.65,58.69 U1.AT1
ENA: length 1
  TOP w0.305: R3094.2 126.28,84.09 U2529.9
ENBLT: length 14.3
  TOP w0.102: v2(128.52,81.62) 128.83,81.93 R541.1
  LAY3 w0.102: v2(139.43,79.9) 138.86,79.33 132.31,79.33 129.93,81.72 128.62,81.72 v2(128.52,81.62)
  BOTTOM w0.102: v2(139.43,79.9) 139.75,80.22 U2526.23
ENPVCC/I2C_ADDR: length 1.3
  TOP w0.305: R2995.1 137.69,83.23 v2(137.67,83.21)
  BOTTOM w0.102: U2526.33 v2(137.67,83.21)
ENSWREG: length 5.4
  BOTTOM w0.102: R311.2 132.57,40 R312.1 131.06,38.79 130.35,39.5 U9.33
EOPIO_RCOMP: length 2.3
  TOP w0.203: U1.H65 v2(223.68,73.03)
  BOTTOM w0.254: R44.1 222.52,71.87 v2(223.68,73.03)
EVDD10: length 36.6
  TOP w0.305: v2(130.43,42.17) 130.43,43.28 129.95,43.76 v2(129.95,47.34)
  TOP w0.406: v2(121.58,34.72) 122.45,35.58 122.45,36.79 v2(122.78,37.12)
  BOTTOM w0.203: C389.1 126.57,36.1 126.4,36.26 U9.41 ; 122.13,39.1 U9.3 ; 122.13,39.1 121.85,38.81 C391.1 ; 122.13,39.1 v2(122.14,39.11) ; C392.1 121.17,40.3 v2(122.14,40.3) U9.6 ; C390.1 122.41,34.63 122.41,35.61 122.89,36.09 123.74,36.09 124.8,37.15 U9.45 ; U9.13 123.6,44.59 v2(123.44,44.75) ; C393.1 121.78,41.79 v2(122.07,41.5) U9.9 ; v2(130.43,42.17) 130.43,41.61 C387.1 130.11,41.1 U9.29 ; U9.21 126.8,44.37 C388.1 127.12,45.6 128.58,47.06 C386.1
  BOTTOM w0.305: 126.9,31.56 126.9,32.7 126.01,33.59 126.01,34.78 126.37,35.13 C389.1 ; C390.1 121.8,34.5 v2(121.58,34.72) ; v2(129.95,47.34) 129.59,47.34 C386.1
  BOTTOM w0.406: C397.1 123.12,44.75 v2(123.44,44.75)
  vias: v1(127.65,31.58)
EXT_BOOT_STALL_STRAP: length 6.7
  TOP w0.076: U1.AM7 189.95,61.19 189.5,60.74 189.5,60.35 189.4,60.24 188.59,60.24 188.49,60.35 185.73,60.35 184.77,59.38 R733.1
FAN_BACK: length 4.9
  TOP w0.203: CN25.2 163.6,16.69 162.73,15.82 D18.P 162.35,15.81 R609.2 R608.2
FAN_PWMIN: length 138.9
  TOP w0.203: CN25.3 163.63,15.69 163.19,15.25 163.19,13.01 162.59,12.42 159.43,12.42 156.36,15.49 v2(156.36,18.54)
  LAY3 w0.203: v2(63.39,59.79) 63.39,58.67 62.87,58.15 62.87,56.21 63.51,55.57 63.51,50.95 v2(63.48,50.92)
  LAY6 w0.203: v2(156.36,18.54) 151.35,23.54 151.35,27.72 140.48,38.59 139.15,38.59 134.5,43.23 130.76,43.23 129.96,44.03 120.86,44.03 119.69,45.19 115.85,45.19 112.13,48.92 96.53,48.92 93.26,45.65 90.94,45.65 89.9,46.69 89.9,47.53 88.42,49 74.87,49 72.95,50.92 v2(63.48,50.92)
  BOTTOM w0.203: U22.24 62.42,61.06 63.01,60.47 R414.1 63.12,60.06 v2(63.39,59.79)
FLASH_SPI_CLK: length 13.4
  TOP w0.076: 185.41,57 185.41,57.22 185.79,57.6 186.72,57.6 186.85,57.47 186.85,57.32 186.9,57.26 187.07,57.26 187.13,57.33 187.13,57.52 187.22,57.6 187.77,57.6 187.84,57.53 187.84,57.42 187.76,57.34 U1.AV2
  TOP w0.102: 185.41,57 184.63,56.22 183.46,56.22 179.94,52.7 178.44,52.7 R137.1
FLASH_SPI_CS*: length 31.3
  TOP w0.076: U1.AU3 187.57,57.78 185.7,57.78 184.51,56.59
  TOP w0.102: 176.13,46.16 177.26,47.29 177.26,52.36 177.88,52.98 179.71,52.98 183.32,56.59 184.51,56.59
  TOP w0.109: 176.13,46.16 175.9,45.93 175.9,39.63 175.42,39.15 175.42,38.72 175.16,38.46 R708.2 174.75,39.54 175.26,40.06 U42.1
FLASH_SPI_D<2>: length 25.2
  TOP w0.076: U1.AW2 187.05,56.88 186.41,56.88 185.84,56.32 185.84,56
  TOP w0.102: R136.1 179.06,37.51 R87.1 179.63,38.05 179.63,51.61 182.92,54.91 184.75,54.91 185.84,56
FLASH_SPI_D<3>: length 16.7
  TOP w0.076: 184.68,57.12 185.85,58.3 188.37,58.3 188.48,58.19 U1.AU4
  TOP w0.102: 176.13,53.51 179.79,53.51 183.39,57.12 184.68,57.12
  TOP w0.109: 176.13,53.51 175.79,53.51 R86.2 175.23,51.9 R711.1
FLASH_SPI_MISO: length 29.2
  TOP w0.076: 186.13,55.97 186.45,56.29 186.78,56.29 186.97,56.48 187.34,56.48 187.63,56.78 U1.AW3
  TOP w0.102: 177.91,36.42 178.99,36.42 180.41,37.84 180.41,44.39 180.12,44.69 180.12,51.71 182.99,54.58 184.74,54.58 186.13,55.97
  TOP w0.109: R138.1 177.1,36.42 177.91,36.42
FLASH_SPI_MOSI: length 11.4
  TOP w0.076: 185.96,56.72 186.29,57.04 188.08,57.04 188.15,57.12 U1.AV3
  TOP w0.102: 185.96,56.72 185.17,55.93 183.52,55.93 179.7,52.1 R139.1
FMISO: length 14.5
  TOP w0.109: U24.2 55.71,62.11 55.22,62.61 55.22,65.08 53.66,66.64 v2(51.94,66.64)
  BOTTOM w0.109: v2(51.94,66.64) 51.29,66.64 50.79,67.14 50.79,68.73 50.32,69.2 U22.103
FMOSI: length 7.2
  TOP w0.109: v2(50.08,68.55) 49.78,68.25 U24.5
  BOTTOM w0.109: U22.102 49.92,68.84 50.08,68.68 v2(50.08,68.55)
FSCE#: length 16.4
  TOP w0.109: v2(52.08,65.79) 53.76,65.79 54.67,64.88 54.67,62.02 55.85,60.84 U24.1
  BOTTOM w0.109: v2(52.08,65.79) 50.74,65.79 49.52,67.01 U22.101
FSCK: length 10.3
  TOP w0.109: U24.6 50.89,63.38 51.43,63.92 51.43,67.49 v2(52.02,68.08)
  BOTTOM w0.109: U22.105 51.12,69.47 52.02,68.57 v2(52.02,68.08)
GA20: length 2
  BOTTOM w0.102: U22.126 59.52,73.62 R402.2
GL834L_3V3: length 35.4
  TOP w0.305: 77.34,100.86 77.68,100.86 77.68,100.86 ; 77.34,100.86 v2(74.76,100.86) ; 77.34,100.86 77.68,101.21 ; 77.68,100.86 82.38,96.16 v2(82.38,95.36) ; 77.68,100.86 77.68,101.21 ; 77.68,101.21 78.06,101.58 78.06,102.59 v2(77.31,103.34) 76.83,103.82 74.01,103.82 v2(73.16,102.96) 73.16,102.12 71.85,100.82 v2(70.93,100.82)
  BOTTOM w0.203: U95.1 76.65,98.41 76.98,98.75 C2784.1
  BOTTOM w0.254: 71.53,100.81 C2783.2 ; 71.53,100.81 71.53,100.32 71.92,99.93 72.32,99.93 72.77,99.49 U95.19 ; 71.53,100.81 71.53,100.82 ; C2782.1 75.26,100.47 74.77,99.97 U95.23
  BOTTOM w0.305: v2(77.31,103.34) 77.68,102.96 FB19.1 77.69,102.41 C2787.1 C2790.1 77.69,98.75 C2784.1 ; C2782.1 75.25,100.86 v2(74.76,100.86) ; 71.53,100.82 v2(70.93,100.82) ; R3008.1 v2(73.16,102.96) ; FB20.2 v2(82.38,95.36)
GPO: length 1.7
  BOTTOM w0.102: U9.38 127.6,36.01 R328.2
GPP_B_CORE_VID0: length 28.7
  TOP w0.076: U1.AN11 193.06,60.54 v2(193.3,60.78)
  LAY3 w0.102: v2(172.74,56.93) 172.52,57.15 172.52,58.4 172.41,58.52 172.41,59.67 172.52,59.79 172.52,60.83 173.72,62.02 175.3,62.02 176.5,60.83 185.58,60.83 185.98,60.42 189.55,60.42 189.97,60.84 191.22,60.84 191.75,61.37 192.71,61.37 v2(193.3,60.78)
  BOTTOM w0.102: TP2.1 173.77,55.9 v2(172.74,56.93)
GPP_B_CORE_VID1: length 26.9
  TOP w0.076: U1.AN13 193.7,60.54 v2(193.3,60.15)
  LAY3 w0.102: v2(172.71,56.12) 173.35,56.75 173.35,58.06 172.61,58.8 172.61,59.41 172.75,59.55 175.07,59.55 176.12,60.59 185.15,60.59 185.69,60.04 189.57,60.04 190.16,60.64 191.46,60.64 192,61.18 192.54,61.18 192.84,60.88 192.84,60.61 v2(193.3,60.15)
GPP_C_5_SML0ALERTB: length 8.7
  TOP w0.076: 180.39,66.94 182.48,66.94 182.85,67.31 U1.W1
  TOP w0.102: R732.1 180.39,66.94
GPP_G_1: length 17.8
  TOP w0.076: U1.AB13 193.64,66.06 v2(193.44,65.81)
  TOP w0.102: v2(177.88,66.25) 177.75,66.12 R632.2
  LAY3 w0.076: 182.01,65.34 183.94,65.34 184.22,65.63 188.3,65.63 188.85,66.18 193.08,66.18 v2(193.44,65.81)
  LAY3 w0.102: v2(177.88,66.25) 178.78,65.34 182.01,65.34
GT_BOOT: length 0.8
  BOTTOM w0.254: U50.2 211.01,96.82
  BOTTOM w0.508: R249.1 211.02,96.83 211.01,96.82
GT_CSP: length 16.5
  BOTTOM w0.203: U103.7 234.67,89.52 233.67,90.51
  BOTTOM w0.305: R184.1 229.49,98.24 R205.2 R204.1 R168.1 229.3,95.98 229.98,95.31 232.47,95.31 232.67,95.1 C297.2 232.16,94.25 231.61,94.25 231.12,93.75 231.12,92.27 231.64,91.75 233.2,91.75 233.67,91.28 233.67,90.51
GT_FCCM: length 34.5
  LAY6 w0.635: v1(207.76,97.21) 207.76,97.07 208.89,95.94 209.99,95.94 210.43,96.38 229.16,96.38 229.85,97.07 233.52,97.07 v1(235.15,95.45)
  BOTTOM w0.203: 235.81,92.14 236.17,91.77 U103.11
  BOTTOM w0.254: U50.7 208.15,96.82 v1(207.76,97.21)
  BOTTOM w0.635: 235.81,92.14 235.15,92.8 v1(235.15,95.45)
GT_HG_DRV: length 4.8
  BOTTOM w0.254: 210.46,97.83 U50.1
  BOTTOM w0.635: 210.46,97.83 210.56,97.93 R254.1
GT_LG_DRV: length 14
  BOTTOM w0.254: U50.5 208.56,95.3 208.73,95.13
  BOTTOM w0.635: R256.1 219.75,93.63 218.53,92.41 211.45,92.41 208.73,95.13
GT_PHASE: length 25
  LAY6 w0.635: v1(208.56,97.88) 219.29,97.88 220.22,98.81 v1(222.94,98.81)
  BOTTOM w0.254: U50.8 v1(208.56,97.88)
  BOTTOM w0.305: v2(228.43,98.28) 228.43,98.84 R184.2
  BOTTOM w0.635: C738.1 222.06,96.83 v1(223.22,97.99)
GT_PWM: length 29.3
  LAY3 w0.635: v1(236.57,92.44) 234.02,92.44 232,94.46 217.09,94.46 v1(216.34,93.71)
  BOTTOM w0.203: U103.12 v1(236.57,92.44)
  BOTTOM w0.254: 211.23,95.94 210.84,96.32 U50.3
  BOTTOM w0.635: v1(216.34,93.71) 214.66,95.39 211.78,95.39 211.23,95.94
H_PECI_EC: length 197
  TOP w0.102: U1.A54 v2(217.31,78.13)
  LAY3 w0.087: v2(57.32,88.73) 57.32,83.29 57.51,83.1 57.51,74.34 55.91,72.74 v2(55.91,70.56)
  LAY6 w0.087: v2(217.31,78.13) 217.31,79.41 216.31,80.41 216.31,84.43 214.65,86.09 207.69,86.09 207.18,86.6 205.86,86.6 201.14,91.32 201.14,91.72 200.49,92.36 191.6,92.36 190.75,91.51 181.07,91.51 179.76,92.82 171.52,92.82 169.98,94.36 150.75,94.36 142.41,86.01 127.39,86.01 125.85,87.55 105.48,87.55 104.35,86.42 90.57,86.42 88.22,88.77 57.36,88.77 v2(57.32,88.73)
  BOTTOM w0.109: U22.117 55.92,70.57 v2(55.91,70.56)
HDA_BITCLK: length 240.9
  TOP w0.076: R621.1 196.23,47.95 196,47.72 196,47.33 197.17,46.16 197.17,44.11
  TOP w0.102: 197.17,44.11 197.17,38.85 195.51,37.18
  TOP w0.109: 195.51,37.18 193.49,37.18 180.93,24.62 170.19,24.62 168.41,26.4 166.35,26.4 164.27,28.48 151.62,28.48 141.29,38.81 141.29,42.25 125.85,57.69 113.61,57.69 104.53,66.77 93.01,66.77 84.75,58.51 72.62,58.51 68.16,54.05 66.29,54.05 65.13,52.89 47.19,52.89 30.27,35.97 v2(27.3,35.97)
  BOTTOM w0.109: v2(27.3,35.97) 27.3,32.52 25.35,30.57 25.35,23.88 C455.2 21.54,20.07 19.09,20.07 18.18,19.16 U16.6
HDA_RST#: length 269.8
  TOP w0.076: R623.1 197.83,46.64 198.29,46.19 198.29,44.11
  TOP w0.102: 195.66,36.34 198.29,38.97 198.29,44.11
  TOP w0.109: v2(29.47,35.45) 30.47,35.45 47.4,52.38 67.71,52.38 73.34,58.02 84.95,58.02 93.21,66.28 104.33,66.28 113.4,57.2 125.65,57.2 135.45,47.4 135.45,46.46 140.8,41.12 140.8,38.6 151.41,27.99 164.03,27.99 166.29,25.73 168.36,25.73 169.96,24.13 181.63,24.13 193.85,36.34 195.66,36.34
  LAY3 w0.087: v2(19.17,14.03) 19.18,14.03 19.72,14.56 19.72,28.37 v2(20.88,29.54)
  BOTTOM w0.109: v2(20.88,29.54) 20.65,29.3 R372.1 21.57,28.77 21.97,29.18 R373.2 ; v2(29.47,35.45) 29.47,32.93 26.52,29.97 26.52,20.51 24.54,18.53 24.54,13.97 23.55,12.98 19.72,12.98 19.17,13.53 v2(19.17,14.03) 19.17,14.73 18.17,15.73 18.17,16.86 17.87,17.16 U16.11
HDA_SDATAIN0: length 243.6
  TOP w0.076: 189.9,44.7 192.27,47.07 194.12,47.07 194.66,47.61 194.66,49.54 197.21,52.09 197.21,53.49 198.02,54.29 198.02,55.7 U1.BA21
  TOP w0.102: 189.9,44.7 187.28,42.08 187.28,36.54 186.91,36.18
  TOP w0.109: 186.91,36.18 177.86,27.12 173.77,27.12 173.26,26.61 171.49,26.61 170.99,27.12 170.26,27.12 167.11,30.27 152.36,30.27 143.08,39.55 143.08,43 126.59,59.49 114.52,59.49 105.85,68.16 92.1,68.16 83.79,59.85 72.05,59.85 68.12,55.91 48.23,55.91 30.31,37.99 28.64,37.99 v2(27.75,37.11)
  BOTTOM w0.109: v2(27.75,37.11) 27.83,37.03 27.83,32.36 25.84,30.37 25.84,22.46 22.01,18.63 21.44,18.63 21,18.19 C457.2 20.93,18.18 R362.2
HDA_SDATAOUT: length 229.3
  TOP w0.102: 188.87,36.18 188.87,38.74 189.53,39.4 191.89,39.4 193.18,40.7 R626.1
  TOP w0.109: v2(26.6,36.36) 26.79,36.55 30.06,36.55 47.29,53.77 53.32,53.77 53.65,54.1 65.11,54.1 65.63,54.62 68.04,54.62 72.42,59 84.14,59 92.45,67.31 105.5,67.31 114.17,58.64 126.24,58.64 142.23,42.65 142.23,39.2 152.01,29.42 164.66,29.42 166.37,27.71 168.48,27.71 170.73,25.46 178.54,25.46 188.87,35.78 188.87,36.18
  BOTTOM w0.109: v2(26.6,36.36) 26.6,32.52 24.86,30.78 24.86,24.48 21.64,21.26 19.79,21.26 C458.2 18.09,19.56 U16.5
HDA_SDOUT: length 14.2
  TOP w0.076: U1.BB22 198.39,54.53 198.39,54.14 197.76,53.5 197.76,51.72 195.8,49.77 195.8,47.58 194.68,46.46 Q59.2 194.65,45.41 Q51.3 192.23,44.86 192.36,44.74
  TOP w0.102: R624.1 192.36,44.74
HDA_SYNC: length 235.3
  TOP w0.102: R620.1 187.72,39.83 187.72,36.32 187.58,36.18
  TOP w0.109: 187.58,36.18 178.11,26.7 174.22,26.7 173.78,26.26 171.34,26.26 170.9,26.7 170.08,26.7 166.93,29.85 152.19,29.85 142.66,39.38 142.66,42.82 126.42,59.07 114.34,59.07 105.68,67.74 92.27,67.74 83.96,59.43 72.24,59.43 67.82,55.01 64.99,55.01 64.76,54.78 50.88,54.78 50.64,55.03 47.93,55.03 30.13,37.22 v2(28.63,37.22)
  BOTTOM w0.109: v2(28.63,37.22) 28.63,32.68 26.18,30.23 26.18,21.61 24.2,19.63 24.2,14.36 23.77,13.94 20.4,13.94 C456.2 19.58,13.91 19.58,14.8 18.51,15.86 18.51,17.1 18.05,17.56 U16.10
HP_OUT_L: length 25.2
  TOP w0.305: v2(7.78,18.73) 9.35,20.3 9.35,23.95 12.29,26.88 23.14,26.88 24.15,25.87 C421.1 R363.1 25.11,24.13 R365.2
  BOTTOM w0.203: v2(7.78,18.73) 7.83,18.68 R350.1
HP_OUT_R: length 24.8
  TOP w0.305: R366.2 25.42,26.9 R364.1 24.44,26.71 C422.1 23.96,26.7 23.26,27.4 12.16,27.4 8.88,24.13 8.88,20.61 v2(7.78,19.5)
  BOTTOM w0.203: v2(7.78,19.5) 7.78,19.5 R349.1
HSON: length 2.8
  BOTTOM w0.109: C394.2 129.32,44.89 128.55,44.89 127.99,44.34 127.99,44.33 127.6,43.94 U9.23
HSOP: length 2.8
  BOTTOM w0.109: C395.2 127.77,44.43 127.77,44.42 127.2,43.85 U9.22
I2C_CLK1: length 6.3
  BOTTOM w0.109: R384.2 55.49,73.4 55.49,73.15 55.12,72.78 U22.115 ; R384.2 55.14,73.74 R396.2 ; R384.2 55.22,73.74 55.57,74.1 55.57,75.47 54.74,76.3 R434.1
I2C_CLK2_LVDS: length 6.6
  TOP w0.102: U2525.6 138.14,76.15 R2991.2 138.02,76.88 v2(138.12,76.98)
  BOTTOM w0.102: v2(138.12,76.98) 138.31,77.17 138.31,79.67 138.95,80.32 U2526.25
I2C_CLK2_THEM: length 225
  TOP w0.109: U5.8 v2(242.51,79.39)
  LAY3 w0.087: v2(54.74,77.95) 54.74,93.57 v2(55.71,94.53)
  LAY6 w0.087: v2(55.71,94.53) 56.04,94.2 87.81,94.2 89.66,92.36 103.89,92.36 105.24,93.71 129.6,93.71 133.86,89.44 137.42,89.44 137.64,89.66 143.1,89.66 150.58,97.14 172.69,97.14 175.1,94.72 181.26,94.72 182.2,93.79 189.34,93.79 191.88,96.33 200.84,96.33 206.4,90.77 207.29,90.77 208.5,89.56 222.64,89.56 225.68,86.52 232.13,86.52 232.92,87.31 236.49,87.31 237.54,86.26 239.02,86.26 240.19,85.09 241.56,85.09 242.69,83.95 242.69,79.58 v2(242.51,79.39)
  BOTTOM w0.109: R434.2 v2(54.74,77.95)
I2C_CLK3: length 1.8
  BOTTOM w0.109: R379.2 44.7,69.46 U22.94
I2C_DATA1: length 6
  BOTTOM w0.109: R397.2 57.04,73.74 R387.2 ; R387.2 55.8,74.18 55.8,76.14 R437.1 ; R387.2 56.24,73.17 55.52,72.45 U22.116
I2C_DATA2_LVDS: length 6.8
  TOP w0.102: U2525.5 139.41,75.72 R2992.2 138.86,76.79 v2(138.67,76.98)
  BOTTOM w0.102: v2(138.67,76.98) 138.67,76.99 138.67,79.72 139.35,80.41 U2526.24
I2C_DATA2_THEM: length 225.5
  TOP w0.109: U5.7 v2(243.16,79.38)
  LAY3 w0.087: v2(55.57,78) 55.57,93.48 56.36,94.27 v2(56.36,94.69)
  LAY6 w0.087: v2(243.16,79.38) 243.16,84.4 242,85.56 240.38,85.56 239.21,86.72 237.74,86.72 236.69,87.78 233.14,87.78 232.21,86.85 226.01,86.85 222.84,90.02 208.7,90.02 207.48,91.24 206.63,91.24 201.06,96.81 191.56,96.81 189.04,94.29 182.36,94.29 181.45,95.21 175.3,95.21 172.74,97.77 150.53,97.77 142.9,90.14 137.42,90.14 137.2,89.92 134.06,89.92 129.66,94.33 104.98,94.33 103.5,92.85 89.86,92.85 88.01,94.69 v2(56.36,94.69)
  BOTTOM w0.109: R437.2 55.57,78 v2(55.57,78)
